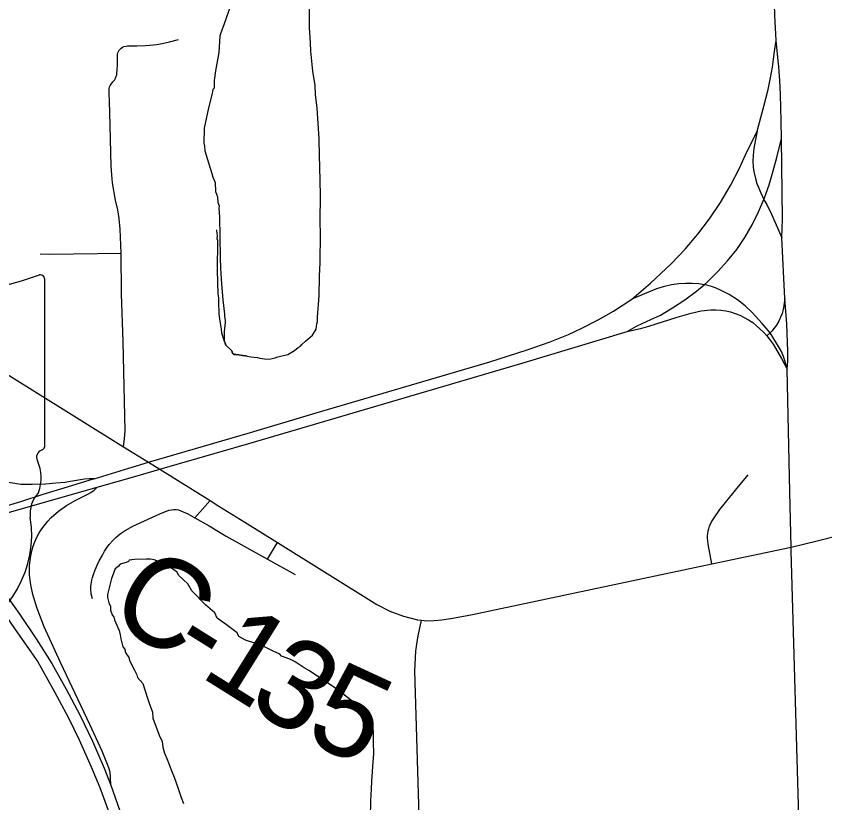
# Model space of a CAD drawing. Extents: x 63.4 to 97.4, y 0.4 to 22.4.
# Drawn here: x 68.633 to 69.147, y 15.543 to 16.043 of the extents above; entities that cross this region are included whole.
import ezdxf

# ---------------------------------------------------------------- set-up
doc = ezdxf.new("R2010")
doc.units = 0
for name, color, linetype in [('GM_X_County_Road', 7, 'Continuous'), ('GM_X_County_Road_Text', 7, 'Continuous'), ('GM_X_Interchange_Ramps', 7, 'Continuous'), ('GM_X_Minor_River', 7, 'Continuous'), ('GM_X_State_Route', 7, 'Continuous'), ('GM_X_State_Shield', 7, 'Continuous'), ('GM_X_Township_Road', 7, 'Continuous')]:
    doc.layers.add(name, color=color, linetype=linetype)

msp = doc.modelspace()

# ---------------------------------------------------------------- linework, layer by layer
at = {"layer": 'GM_X_County_Road'}
msp.add_line((69.0751694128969, 15.694626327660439), (69.12543201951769, 15.705195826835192), dxfattribs=at)
for points in [[(68.19297940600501, 16.084393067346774), (68.19990770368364, 16.08009316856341), (68.23713398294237, 16.05758095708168), (68.52195753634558, 15.880689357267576), (68.64326757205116, 15.805292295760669), (68.70134703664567, 15.769109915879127)], [(69.12153605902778, 15.863210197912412), (69.11964087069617, 15.901884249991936), (69.12006337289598, 15.913802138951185), (69.11927423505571, 15.964866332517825)], [(69.12285954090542, 15.81834726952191), (69.12328209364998, 15.823560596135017), (69.12342500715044, 15.82991721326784), (69.12283471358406, 15.847085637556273), (69.12153605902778, 15.863210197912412)], [(69.12543201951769, 15.705195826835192), (69.12463669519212, 15.740141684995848), (69.12285954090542, 15.81834726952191)], [(68.70134703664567, 15.769109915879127), (68.71726652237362, 15.759279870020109), (68.72442470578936, 15.754731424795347), (68.75627613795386, 15.734878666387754)], [(69.12543201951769, 15.705195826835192), (69.14194183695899, 15.709247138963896), (69.26553232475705, 15.740545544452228), (69.35206430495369, 15.762194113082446)], [(68.75627613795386, 15.734878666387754), (68.76189334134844, 15.731392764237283), (68.77827884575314, 15.721171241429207), (68.7991755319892, 15.708128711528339), (68.86233156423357, 15.668752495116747), (68.87055848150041, 15.664589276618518), (68.87916447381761, 15.661314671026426), (68.8880438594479, 15.659015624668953), (68.89057281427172, 15.658748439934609)], [(69.13285738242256, 15.44518354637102), (69.13227951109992, 15.46765852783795), (69.1254879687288, 15.702952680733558), (69.12543201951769, 15.705195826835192)], [(68.89057281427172, 15.658748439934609), (68.89408976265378, 15.658394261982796), (68.89877492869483, 15.65860549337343), (68.90362158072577, 15.658941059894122), (68.91055608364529, 15.65999739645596), (68.9229461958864, 15.662520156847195), (69.0751694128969, 15.694626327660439)]]:
    msp.add_lwpolyline(points, dxfattribs=at)
at = {"layer": 'GM_X_Interchange_Ramps'}
for points in [[(69.10383941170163, 15.969588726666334), (69.10277066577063, 15.964331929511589), (69.10180134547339, 15.958745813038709), (69.10137258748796, 15.954340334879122), (69.10116133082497, 15.950692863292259), (69.10135393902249, 15.946890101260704), (69.10179513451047, 15.944019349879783), (69.1027706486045, 15.939632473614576), (69.1037399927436, 15.936301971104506), (69.10484606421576, 15.933381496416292), (69.10622547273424, 15.930405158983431), (69.10821388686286, 15.926328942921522), (69.10863020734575, 15.9254838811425), (69.10998478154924, 15.92302328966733), (69.1129052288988, 15.91692762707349), (69.11540933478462, 15.911708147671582), (69.11964087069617, 15.901884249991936)], [(69.12285954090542, 15.81834726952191), (69.12171002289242, 15.823138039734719), (69.12061641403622, 15.82646860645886), (69.11928045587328, 15.829606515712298), (69.11623577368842, 15.834950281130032), (69.11438408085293, 15.837758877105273), (69.11214092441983, 15.841555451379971), (69.10697735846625, 15.847402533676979), (69.1007449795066, 15.85433083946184), (69.0962587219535, 15.85861827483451), (69.09140580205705, 15.862483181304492), (69.08619252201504, 15.865851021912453), (69.08067474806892, 15.868696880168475), (69.07781024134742, 15.869896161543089), (69.07487736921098, 15.870902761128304), (69.07188235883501, 15.871698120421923), (69.07015496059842, 15.872077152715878), (69.0668927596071, 15.872543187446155), (69.06266125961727, 15.872866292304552), (69.05829302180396, 15.872841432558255), (69.05406148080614, 15.872617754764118), (69.04946336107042, 15.871946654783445), (69.04409467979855, 15.870672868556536), (69.0399687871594, 15.869349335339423), (69.03492950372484, 15.867348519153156), (69.02434756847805, 15.862924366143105)], [(69.12153605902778, 15.863210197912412), (69.120628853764, 15.85741904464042), (69.12020008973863, 15.855530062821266), (69.11972162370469, 15.853784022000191), (69.1188206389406, 15.851466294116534), (69.1176276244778, 15.848887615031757), (69.11614876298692, 15.846439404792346), (69.11452076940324, 15.844221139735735), (69.11337124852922, 15.842829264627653), (69.11214092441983, 15.841555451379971), (69.1101152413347, 15.839616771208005)], [(69.02135876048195, 15.84228244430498), (69.03066069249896, 15.844351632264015), (69.0350786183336, 15.845700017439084), (69.05296166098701, 15.851522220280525), (69.06206472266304, 15.854063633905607), (69.06822872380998, 15.855374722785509), (69.07448590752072, 15.856051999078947), (69.0776300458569, 15.8560831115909), (69.08077415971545, 15.855890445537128), (69.08389346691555, 15.855455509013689), (69.0869692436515, 15.854784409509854), (69.08997663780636, 15.853864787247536), (69.09290331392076, 15.852702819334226), (69.09572434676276, 15.851317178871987), (69.09844591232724, 15.849726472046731), (69.10104944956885, 15.847955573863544), (69.10354115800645, 15.846029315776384), (69.10567246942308, 15.844121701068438), (69.10814553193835, 15.841723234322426), (69.1101152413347, 15.839616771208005), (69.11219684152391, 15.836901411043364), (69.11400504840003, 15.834316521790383), (69.11564546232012, 15.831625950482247), (69.11940472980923, 15.825076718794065), (69.12285954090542, 15.81834726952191)], [(68.68268729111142, 15.748610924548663), (68.67938780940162, 15.748697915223), (68.67646739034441, 15.748405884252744), (68.66889910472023, 15.74711967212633), (68.6640027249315, 15.746423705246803), (68.65829851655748, 15.745839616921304), (68.65200404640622, 15.745373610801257), (68.64326758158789, 15.745019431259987), (68.63609696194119, 15.745125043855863), (68.6268696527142, 15.746554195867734), (68.61779143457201, 15.748704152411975), (68.61184491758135, 15.750543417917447), (68.60314575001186, 15.753886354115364), (68.59188029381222, 15.759155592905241), (68.56151392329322, 15.77495080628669), (68.4764049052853, 15.820304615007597), (68.45423443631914, 15.831619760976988), (68.43736423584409, 15.839610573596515), (68.42021443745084, 15.846998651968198), (68.41427411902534, 15.84950898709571), (68.41085038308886, 15.850503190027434), (68.40422035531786, 15.851310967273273), (68.3981309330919, 15.85155332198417)], [(68.68268729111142, 15.748610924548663), (68.66551885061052, 15.743279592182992), (68.6500281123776, 15.738613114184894), (68.6358297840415, 15.734008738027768), (68.58899091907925, 15.7201397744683)], [(68.59896389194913, 15.718909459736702), (68.68453898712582, 15.743292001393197)]]:
    msp.add_lwpolyline(points, dxfattribs=at)
at = {"layer": 'GM_X_Minor_River'}
for points in [[(68.77990732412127, 15.82655280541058), (68.7821762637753, 15.826141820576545), (68.78633914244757, 15.825704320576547), (68.78785240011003, 15.825302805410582), (68.79087891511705, 15.824880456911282), (68.79391111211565, 15.824836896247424), (68.79771414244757, 15.825541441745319), (68.79847740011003, 15.82591265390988), (68.8011421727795, 15.826634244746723), (68.80304368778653, 15.826986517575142), (68.8057065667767, 15.827708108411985), (68.80991868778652, 15.83030659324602), (68.81221982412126, 15.83217212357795), (68.81374823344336, 15.832910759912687), (68.81452285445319, 15.834039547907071), (68.8168315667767, 15.836285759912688), (68.82143573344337, 15.840016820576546), (68.82376717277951, 15.84378386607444), (68.82419520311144, 15.847194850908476), (68.82459861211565, 15.848708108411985), (68.82463649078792, 15.851365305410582), (68.82559671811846, 15.865024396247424), (68.82578043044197, 15.877554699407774), (68.82628800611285, 15.886281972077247), (68.82655694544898, 15.90450735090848), (68.82628800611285, 15.912105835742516), (68.82654179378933, 15.929192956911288), (68.82628990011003, 15.937931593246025), (68.82604368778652, 15.947049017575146), (68.8257671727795, 15.95388992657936), (68.8255493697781, 15.96490507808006), (68.82431830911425, 15.984291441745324), (68.82330883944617, 15.993039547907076), (68.82301338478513, 15.99874219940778), (68.82163080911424, 16.007874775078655), (68.8202993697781, 16.020427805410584), (68.81999823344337, 16.025749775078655), (68.81938459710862, 16.03563045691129), (68.81947550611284, 16.041706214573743), (68.81925770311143, 16.052723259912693)], [(68.76954558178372, 16.050009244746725), (68.76519520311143, 16.037916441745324), (68.76282399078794, 16.031494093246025), (68.76242247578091, 16.029982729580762), (68.7618940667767, 16.019734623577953), (68.75982588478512, 16.007992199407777), (68.75897740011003, 16.001927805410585), (68.75890543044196, 15.996990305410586), (68.75813649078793, 15.996242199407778), (68.75771793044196, 15.99358879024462), (68.75530883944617, 15.98450735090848), (68.75246414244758, 15.97163613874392), (68.75232588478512, 15.96214560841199), (68.7526762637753, 15.960240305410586), (68.75300959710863, 15.957196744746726), (68.75554179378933, 15.948806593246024), (68.75734861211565, 15.942704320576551), (68.75807209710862, 15.940416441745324), (68.75953800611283, 15.936978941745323), (68.759833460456, 15.931276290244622), (68.76092058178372, 15.92784257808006), (68.76125012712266, 15.924420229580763), (68.76197361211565, 15.922130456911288), (68.76195277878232, 15.920613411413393), (68.76224633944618, 15.914910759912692), (68.76244709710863, 15.90275735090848), (68.76262702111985, 15.889083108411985), (68.76290921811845, 15.882622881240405), (68.7635171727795, 15.87235962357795), (68.76450959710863, 15.86247136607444), (68.76551338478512, 15.853342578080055), (68.76549065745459, 15.851823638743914), (68.76583535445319, 15.84953954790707), (68.76581262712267, 15.848022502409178), (68.76535050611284, 15.842331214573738), (68.76531641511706, 15.840052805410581)], [(68.77990732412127, 15.82655280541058), (68.77877474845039, 15.826948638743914), (68.77687891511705, 15.826977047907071), (68.7746099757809, 15.827388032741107), (68.77271982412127, 15.827795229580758), (68.771583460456, 15.827810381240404), (68.7704565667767, 15.828586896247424), (68.77009861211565, 15.830111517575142), (68.76635808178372, 15.833581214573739), (68.76526527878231, 15.836636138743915), (68.76381830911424, 15.841213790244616), (68.76347550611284, 15.843876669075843), (68.76279179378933, 15.848823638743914), (68.76209861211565, 15.853389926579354), (68.76183914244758, 15.86136909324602), (68.76187323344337, 15.863647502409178), (68.76153232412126, 15.866312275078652), (68.7609906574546, 15.881130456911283), (68.761270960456, 15.900115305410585), (68.76090732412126, 15.901259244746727), (68.76093573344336, 15.903158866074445), (68.76060808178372, 15.906581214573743), (68.76022929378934, 15.906586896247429)], [(68.76531641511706, 15.840052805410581), (68.76526527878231, 15.836636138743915), (68.76635808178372, 15.833581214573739), (68.77009861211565, 15.830111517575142), (68.7704565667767, 15.828586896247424), (68.771583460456, 15.827810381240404), (68.77271982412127, 15.827795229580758), (68.7746099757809, 15.827388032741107), (68.77687891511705, 15.826977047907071), (68.77877474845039, 15.826948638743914), (68.77990732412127, 15.82655280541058)], [(68.85918194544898, 15.596427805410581), (68.85882020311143, 15.597571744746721), (68.85844709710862, 15.597956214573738), (68.85771224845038, 15.599486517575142), (68.85545277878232, 15.60065886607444), (68.85471224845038, 15.601808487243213), (68.85095277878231, 15.604138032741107), (68.84908724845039, 15.606064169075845), (68.8464565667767, 15.607620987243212), (68.84270277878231, 15.610333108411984), (68.83932967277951, 15.61303765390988), (68.8355796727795, 15.615751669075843), (68.83144709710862, 15.618467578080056), (68.82732020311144, 15.621564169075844), (68.82356452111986, 15.623895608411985), (68.81943383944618, 15.62661341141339), (68.8160493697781, 15.628558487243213), (68.81041868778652, 15.63243727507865), (68.80702853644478, 15.63400356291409), (68.80174823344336, 15.63597704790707), (68.80062891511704, 15.637132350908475), (68.79648497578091, 15.63909068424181), (68.7900853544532, 15.642219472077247), (68.78819520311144, 15.642624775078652), (68.78593762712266, 15.643797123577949), (68.7787690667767, 15.64617780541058), (68.77463080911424, 15.648514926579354), (68.77352853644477, 15.650810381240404), (68.76677664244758, 15.655842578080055), (68.7607728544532, 15.660103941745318), (68.75930505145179, 15.663541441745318), (68.75331262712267, 15.668564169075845), (68.74472171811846, 15.677420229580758), (68.74213649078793, 15.682016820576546), (68.7361478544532, 15.687416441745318), (68.73541679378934, 15.689325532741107), (68.72978611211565, 15.693204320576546), (68.725270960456, 15.695545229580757), (68.72074444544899, 15.69712856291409), (68.71847550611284, 15.697539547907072), (68.71582020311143, 15.697577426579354), (68.70823497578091, 15.69730659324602), (68.70481452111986, 15.696975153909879), (68.70442436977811, 15.69622136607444), (68.7028978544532, 15.695484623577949), (68.69909103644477, 15.694397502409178), (68.69793005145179, 15.692895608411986), (68.69601338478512, 15.691403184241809), (68.69364785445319, 15.68535962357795), (68.69122171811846, 15.675141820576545), (68.69119520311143, 15.673242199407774), (68.69190353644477, 15.669814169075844), (68.69300580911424, 15.667520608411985), (68.69297171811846, 15.665242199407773), (68.69406641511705, 15.66218727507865), (68.69518005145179, 15.66065318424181), (68.69553611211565, 15.659128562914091), (68.6962728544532, 15.657600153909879), (68.69846982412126, 15.652251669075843), (68.69918762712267, 15.649583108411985), (68.69953043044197, 15.646920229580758), (68.70097171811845, 15.641963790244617), (68.70208724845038, 15.640427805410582), (68.70244520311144, 15.638903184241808), (68.70280694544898, 15.637759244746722), (68.70466300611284, 15.635073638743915), (68.70501338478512, 15.633170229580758), (68.70833724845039, 15.627047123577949), (68.70980883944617, 15.62398841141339), (68.71016490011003, 15.622461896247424), (68.713520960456, 15.61861909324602), (68.71642436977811, 15.609842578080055), (68.71750770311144, 15.60602818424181), (68.71969899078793, 15.600302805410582), (68.720020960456, 15.596497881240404), (68.72403421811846, 15.585810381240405), (68.72586944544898, 15.581603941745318), (68.72619709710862, 15.57818159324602), (68.72728043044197, 15.57436909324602), (68.72874633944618, 15.570929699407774), (68.73020467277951, 15.567111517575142), (68.73167247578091, 15.563674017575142), (68.73350202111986, 15.55909068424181), (68.73604747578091, 15.551838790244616), (68.7378599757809, 15.546117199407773), (68.73932209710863, 15.542299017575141)], [(68.85809861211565, 15.522766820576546), (68.85841111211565, 15.544030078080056), (68.85890353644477, 15.551617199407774), (68.85897550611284, 15.556554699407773), (68.85991111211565, 15.568692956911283), (68.86036944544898, 15.57400356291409), (68.86009671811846, 15.581223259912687), (68.86019141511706, 15.58767780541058), (68.85918194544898, 15.596427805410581)]]:
    msp.add_lwpolyline(points, dxfattribs=at)
at = {"layer": 'GM_X_State_Route'}
for points in [[(69.11927423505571, 15.964866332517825), (69.11910028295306, 15.97609447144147), (69.11877713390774, 15.99299576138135), (69.1183483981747, 16.001806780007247), (69.11796938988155, 16.00741151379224), (69.11763382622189, 16.01077314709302), (69.11721128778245, 16.01443923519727), (69.115925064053, 16.02725188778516), (69.11508622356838, 16.043289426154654), (69.11415381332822, 16.078246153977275)], [(68.68268729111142, 15.748610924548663), (68.70470865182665, 15.755390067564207), (68.71726652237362, 15.759279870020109), (68.78194495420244, 15.778194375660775), (68.82368234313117, 15.790540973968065), (68.93399414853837, 15.82313805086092), (68.95774913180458, 15.83061314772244), (68.97245075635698, 15.835776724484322), (68.98402688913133, 15.840436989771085), (68.99252720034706, 15.844376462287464), (69.00289786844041, 15.849676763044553), (69.01258504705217, 15.855287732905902), (69.02434756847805, 15.862924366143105), (69.03601688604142, 15.87309619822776), (69.0427898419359, 15.879173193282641), (69.04953791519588, 15.885616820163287), (69.05809414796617, 15.894645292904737), (69.0661471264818, 15.904127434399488), (69.0736657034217, 15.914038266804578), (69.0806001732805, 15.9243654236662), (69.08696301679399, 15.935053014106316), (69.09270448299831, 15.946088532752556), (69.09656940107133, 15.954582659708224), (69.10383941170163, 15.969588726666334), (69.10770432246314, 15.983768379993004), (69.11079256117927, 15.996115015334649), (69.11237083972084, 16.003639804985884), (69.11355143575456, 16.01040654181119), (69.11423494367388, 16.01545824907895), (69.11496816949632, 16.02041058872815), (69.115925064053, 16.02725188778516)], [(69.02135876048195, 15.84228244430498), (69.0272555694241, 15.845637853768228), (69.03078493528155, 15.84733419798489), (69.03637109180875, 15.849906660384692), (69.04239838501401, 15.85269660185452), (69.05009715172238, 15.857474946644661), (69.0578642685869, 15.862458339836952), (69.06527722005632, 15.867957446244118), (69.07015496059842, 15.872077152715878), (69.07230488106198, 15.87394125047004), (69.07892869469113, 15.880372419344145), (69.08513619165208, 15.887207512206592), (69.09088384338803, 15.894427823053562), (69.0960722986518, 15.902064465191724), (69.10068286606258, 15.910055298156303), (69.10478389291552, 15.918331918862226), (69.10821388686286, 15.926328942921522), (69.10854941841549, 15.927254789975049), (69.11148225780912, 15.935531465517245), (69.1139677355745, 15.94441702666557), (69.11631651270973, 15.953016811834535), (69.11844162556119, 15.961523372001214), (69.11927423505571, 15.964866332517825)], [(68.68453898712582, 15.743292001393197), (68.7085673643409, 15.750145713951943), (68.72442470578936, 15.754731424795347), (68.78250415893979, 15.771527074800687), (68.95513940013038, 15.82231163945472), (69.02135876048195, 15.84228244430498)], [(68.69315114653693, 15.554010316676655), (68.69310766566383, 15.559037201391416), (68.69282807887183, 15.562305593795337), (68.69207000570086, 15.564921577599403), (68.68766446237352, 15.575584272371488), (68.67990979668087, 15.592566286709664), (68.66116303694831, 15.631886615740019), (68.65091044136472, 15.654591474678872), (68.64636202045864, 15.666192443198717), (68.64363420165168, 15.675127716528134), (68.64234797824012, 15.681223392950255), (68.64163961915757, 15.687399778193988), (68.64162095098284, 15.69360725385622), (68.64191920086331, 15.696701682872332), (68.6424038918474, 15.699771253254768), (68.64308738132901, 15.70280356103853), (68.64396971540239, 15.705786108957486), (68.6450384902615, 15.708706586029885), (68.6463185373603, 15.711533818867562), (68.64777875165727, 15.714280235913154), (68.64945023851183, 15.716883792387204), (68.65325921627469, 15.721792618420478), (68.65539050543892, 15.724060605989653), (68.66005699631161, 15.72819274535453), (68.66515223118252, 15.731790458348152), (68.67052707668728, 15.734940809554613), (68.67444170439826, 15.73686085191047), (68.67868569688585, 15.73896726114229), (68.68054977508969, 15.74001738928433), (68.68265624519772, 15.741514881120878), (68.68453898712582, 15.743292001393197)], [(68.5754916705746, 15.722547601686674), (68.58033524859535, 15.717573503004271), (68.58352908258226, 15.714298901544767), (68.5869279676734, 15.710813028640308), (68.60124432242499, 15.69468223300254), (68.6103349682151, 15.683777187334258), (68.62101632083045, 15.669460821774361), (68.6325551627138, 15.652832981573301), (68.64677831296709, 15.632271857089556), (68.65750937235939, 15.61328277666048), (68.6662707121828, 15.596773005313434), (68.67310576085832, 15.582767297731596), (68.68071132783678, 15.565685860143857), (68.68632043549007, 15.552518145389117)], [(68.62470105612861, 15.677631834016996), (68.63551908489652, 15.662489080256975), (68.6458649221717, 15.64702318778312), (68.65566392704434, 15.631203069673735), (68.66491612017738, 15.615059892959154), (68.67359043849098, 15.59859358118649), (68.68164341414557, 15.581816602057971), (68.68903150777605, 15.564747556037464), (68.69315114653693, 15.554010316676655)], [(68.68632043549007, 15.552518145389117), (68.68773905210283, 15.548355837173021), (68.69306419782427, 15.533703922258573), (68.6987808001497, 15.51589546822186), (68.70388845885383, 15.49790682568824), (68.70764774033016, 15.48278268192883), (68.71084776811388, 15.467528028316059), (68.71209053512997, 15.460431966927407), (68.7140726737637, 15.449110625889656), (68.71718577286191, 15.427530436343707), (68.72003785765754, 15.402781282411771), (68.72397734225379, 15.359391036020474), (68.734994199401, 15.232345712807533), (68.73826883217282, 15.195144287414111), (68.74453847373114, 15.12387316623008), (68.75652467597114, 14.984388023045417), (68.78657414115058, 14.637228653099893), (68.79476644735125, 14.542747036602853)], [(68.69315114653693, 15.554010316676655), (68.69458654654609, 15.55026966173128), (68.70069458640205, 15.532684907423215), (68.70619371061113, 15.514901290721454), (68.71108388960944, 15.496937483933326), (68.71539622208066, 15.478830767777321), (68.71911820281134, 15.460593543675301), (68.72015590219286, 15.454491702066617), (68.72223126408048, 15.442238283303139), (68.72472296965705, 15.423796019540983), (68.72734517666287, 15.399096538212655), (68.73254601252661, 15.340308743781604), (68.74440178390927, 15.200985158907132), (68.74481807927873, 15.196163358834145), (68.75705908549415, 15.055466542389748), (68.78280241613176, 14.758228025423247), (68.80151799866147, 14.542747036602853)]]:
    msp.add_lwpolyline(points, dxfattribs=at)
at = {"layer": 'GM_X_State_Shield'}
for p, q in [((68.6512687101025, 15.77023079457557), (68.6512687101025, 15.87491619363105)), ((68.65124301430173, 15.770256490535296), (68.6512687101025, 15.77023079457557))]:
    msp.add_line(p, q, dxfattribs=at)
for centre, radius, start, end in [((68.55734679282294, 16.142789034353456), 0.2796157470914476, 275.8444694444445, 288.9064527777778), ((68.6483442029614, 15.875350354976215), 0.0029352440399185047, 351.8620861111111, 97.738), ((68.64813718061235, 15.769826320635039), 0.003141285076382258, 289.6038111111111, 7.734130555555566), ((68.65059061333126, 15.76254557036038), 0.004542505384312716, 107.94398333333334, 210.33696666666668), ((68.62169156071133, 15.749312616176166), 0.02726868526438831, 340.0329638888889, 23.649566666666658), ((68.6617853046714, 15.726421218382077), 0.019839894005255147, 136.80649722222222, 186.92959444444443), ((68.57301040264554, 15.713103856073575), 0.06993829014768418, 292.3088861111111, 8.985838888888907)]:
    msp.add_arc(centre, radius, start, end, dxfattribs=at)
at = {"layer": 'GM_X_Township_Road'}
for p, q in [((68.74671945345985, 15.723886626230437), (68.75627613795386, 15.734878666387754)), ((68.7928251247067, 15.697633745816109), (68.7991755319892, 15.708128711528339)), ((68.7928251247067, 15.697633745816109), (68.81035397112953, 15.68794660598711))]:
    msp.add_line(p, q, dxfattribs=at)
for points in [[(68.69714657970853, 16.006498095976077), (68.69728949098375, 16.0084802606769), (68.6974199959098, 16.011935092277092), (68.69748213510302, 16.014364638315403), (68.69748210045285, 16.016340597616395), (68.69748210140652, 16.017626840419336), (68.69755666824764, 16.018689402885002), (68.69771202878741, 16.019372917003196), (68.69793570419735, 16.019981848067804), (68.69859438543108, 16.021125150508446), (68.69927167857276, 16.021895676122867), (68.6998371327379, 16.022411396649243), (68.7007443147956, 16.023094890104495), (68.70158316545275, 16.023473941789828), (68.70293774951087, 16.023778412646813), (68.70393813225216, 16.023896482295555), (68.70567798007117, 16.02400208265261), (68.70969204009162, 16.024020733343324), (68.71524706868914, 16.02416988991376), (68.71795006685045, 16.024263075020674), (68.72041067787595, 16.024455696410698), (68.72224368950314, 16.024698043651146), (68.72591602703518, 16.02532561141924), (68.73043956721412, 16.026369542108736), (68.73630530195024, 16.027873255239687)], [(68.69973147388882, 15.892029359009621), (68.69919707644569, 15.907402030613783), (68.69847008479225, 15.914230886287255), (68.69758776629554, 15.919736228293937), (68.69629531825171, 15.925738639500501), (68.69438147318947, 15.93673688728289), (68.69385331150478, 15.941838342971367), (68.69356128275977, 15.94743691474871), (68.69254224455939, 15.981699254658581), (68.69236200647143, 15.987962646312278), (68.69217561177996, 15.994325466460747), (68.6922253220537, 15.995636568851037), (68.69227503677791, 15.996649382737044), (68.69247389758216, 15.997817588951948), (68.69285912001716, 15.998805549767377), (68.69338729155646, 15.999638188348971), (68.69444361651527, 16.000949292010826), (68.69559938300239, 16.002117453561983), (68.69627046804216, 16.003434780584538), (68.69672404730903, 16.00457188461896), (68.696953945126, 16.005385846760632), (68.69714657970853, 16.006498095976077)], [(68.64836905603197, 15.891637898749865), (68.65442737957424, 15.891432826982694), (68.69973147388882, 15.892029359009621)], [(68.70134703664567, 15.769109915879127), (68.70195596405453, 15.774341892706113), (68.70227908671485, 15.779076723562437), (68.70099905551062, 15.835814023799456), (68.70001728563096, 15.866192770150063), (68.69973147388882, 15.892029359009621)], [(69.0751694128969, 15.694626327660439), (69.07280198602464, 15.707227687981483), (69.07255343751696, 15.709284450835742), (69.0724043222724, 15.710999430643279), (69.07239811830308, 15.712440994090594), (69.07254724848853, 15.713907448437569), (69.07279578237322, 15.71556025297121), (69.07308784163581, 15.716809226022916), (69.0736222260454, 15.718586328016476), (69.07490842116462, 15.721432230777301), (69.07653020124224, 15.723911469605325), (69.08025222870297, 15.729193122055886), (69.0900760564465, 15.741458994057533), (69.0980793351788, 15.75114613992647)], [(68.6815626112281, 15.672437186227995), (68.68084181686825, 15.675488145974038), (68.6805497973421, 15.678607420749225), (68.680624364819, 15.680191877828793), (68.68071756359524, 15.681732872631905), (68.68119601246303, 15.684299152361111), (68.68158125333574, 15.685920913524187), (68.68214672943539, 15.687828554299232), (68.68329622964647, 15.69079246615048), (68.68453897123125, 15.693849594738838), (68.68583145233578, 15.696490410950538), (68.68788196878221, 15.70015650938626), (68.68921790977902, 15.70273518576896), (68.69053520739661, 15.704630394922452), (68.69208240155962, 15.706848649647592), (68.69450573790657, 15.709477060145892), (68.69638230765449, 15.711334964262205), (68.69919090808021, 15.7136215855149), (68.70240337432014, 15.715926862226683), (68.70721277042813, 15.71852420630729), (68.72432528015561, 15.726353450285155), (68.73019724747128, 15.728652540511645), (68.73173201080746, 15.729019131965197), (68.73324194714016, 15.729180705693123), (68.7348823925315, 15.72911233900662), (68.7362928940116, 15.72885760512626), (68.742065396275, 15.726440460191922), (68.74671945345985, 15.723886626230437)], [(68.74671945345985, 15.723886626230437), (68.75581630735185, 15.71889701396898), (68.76646659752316, 15.71217999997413), (68.7928251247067, 15.697633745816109)], [(69.07075736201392, 14.542747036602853), (69.03563166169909, 14.697215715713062), (69.02710023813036, 14.739897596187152), (68.98129283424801, 14.943122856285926), (68.93501321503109, 15.146242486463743), (68.92160406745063, 15.200575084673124), (68.92010035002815, 15.208963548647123), (68.90441072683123, 15.27635112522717), (68.89840208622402, 15.306847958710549), (68.89605952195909, 15.325339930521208), (68.89484164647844, 15.347044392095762), (68.89408977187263, 15.371172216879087), (68.89169752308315, 15.449558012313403), (68.88635372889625, 15.626642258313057), (68.88704967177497, 15.639057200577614), (68.88765858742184, 15.643605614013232), (68.88849743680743, 15.648856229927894), (68.89057281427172, 15.658748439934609)]]:
    msp.add_lwpolyline(points, dxfattribs=at)

# ---------------------------------------------------------------- texts
at = {"layer": 'GM_X_County_Road_Text'}
for s, height, rotation, p in [('C', 0.05681818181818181, 327.91601599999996, (68.68936367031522, 15.660886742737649)), ('1', 0.056818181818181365, 327.996582, (68.74875085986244, 15.623664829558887)), ('-', 0.05681818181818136, 327.934696, (68.72891979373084, 15.636088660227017)), ('3', 0.05681818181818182, 328.252272, (68.77866408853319, 15.604969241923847)), ('5', 0.05681818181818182, 335.234846, (68.81507823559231, 15.582976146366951))]:
    msp.add_text(s, height=height, rotation=rotation, dxfattribs=at).set_placement(p)

doc.saveas('drawing.dxf')
